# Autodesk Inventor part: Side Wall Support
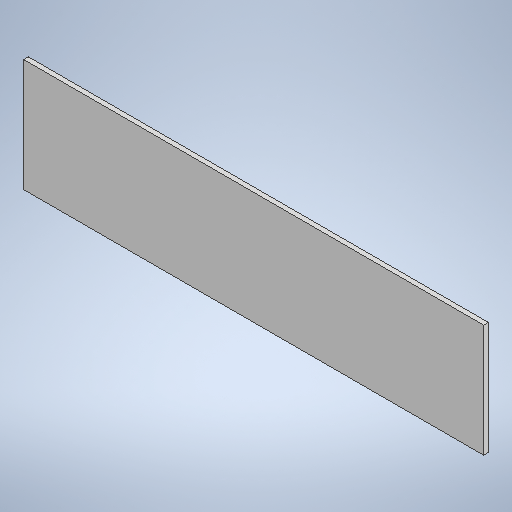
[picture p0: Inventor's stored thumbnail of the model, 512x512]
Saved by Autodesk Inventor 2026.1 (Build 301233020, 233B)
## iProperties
Created: 2026-10
Part Number: Side Wall Support
Material: Generic
Document SubType Name: Modeling
Designer: hp
Density: 1 g/cm^3
Appearance: Default
Author: hp
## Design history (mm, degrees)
sketch "Sketch1"
  geometry: L1 (0, 0)-(540, 0); L2 (540, 120)-(0, 120); L3 (0, 120)-(0, 0); L4 (540, 120)-(540, 0); L5 (50, 120)-(50, 0)
  constraints: 10 end point, 2 point on line, 1 horizontal, 1 parallel, 1 perpendicular, 1 vertical
  dimensions: "d28" = 540 distance of L2.start L2.end; "d29" = 120 distance of L2.end L1.start; "d48" = 50 distance between parallel lines of L3 L5
extrude "Extrusion2" new body sketch "Sketch1" distance "d23" = 5; taper "d24" = 0 deg
body "Solid2"
